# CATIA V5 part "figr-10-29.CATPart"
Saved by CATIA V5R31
Part number: Part1
Bounding box of the stored display mesh (mm): x -60 to 70, y 0 to 100.393, z 0 to 0
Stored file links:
  D:\PROJECTS\Project 2021\US EDITION\CATIA V5 6R 2021\Resources\Part Files\c10_catia_v5_6r2021_prt\c10_catia_v5_6r2021_prt\figr-10-29.CATPart
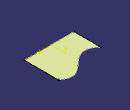
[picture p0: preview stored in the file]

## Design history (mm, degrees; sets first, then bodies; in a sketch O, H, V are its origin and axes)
Set1
  Sweep1: type Segment, GuideCrv (Sketch1; Sketch2), Length1 0, Length2 0
Body1 (main body)
  Sketch1 on xy-plane, origin (0, 0, 0), H (1, 0, 0), V (0, 1, 0)
    line L1 (-60, 0) -> (70, 0)
    point P1 (-60, 0)
    coincidence: P1 H
    horizontal: L1 H
  Sketch2 on xy-plane, origin (0, 0, 0), H (1, 0, 0), V (0, 1, 0)
    spline S1 through (-60, 70) (-20, 60) (40, 100) (70, 90)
